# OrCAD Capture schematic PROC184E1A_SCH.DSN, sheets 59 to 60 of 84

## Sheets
59 67. x4 LANE_PCIe_CONN: size C; title: x1LANE PCIe INTERFACE; note: PROC184_SCH
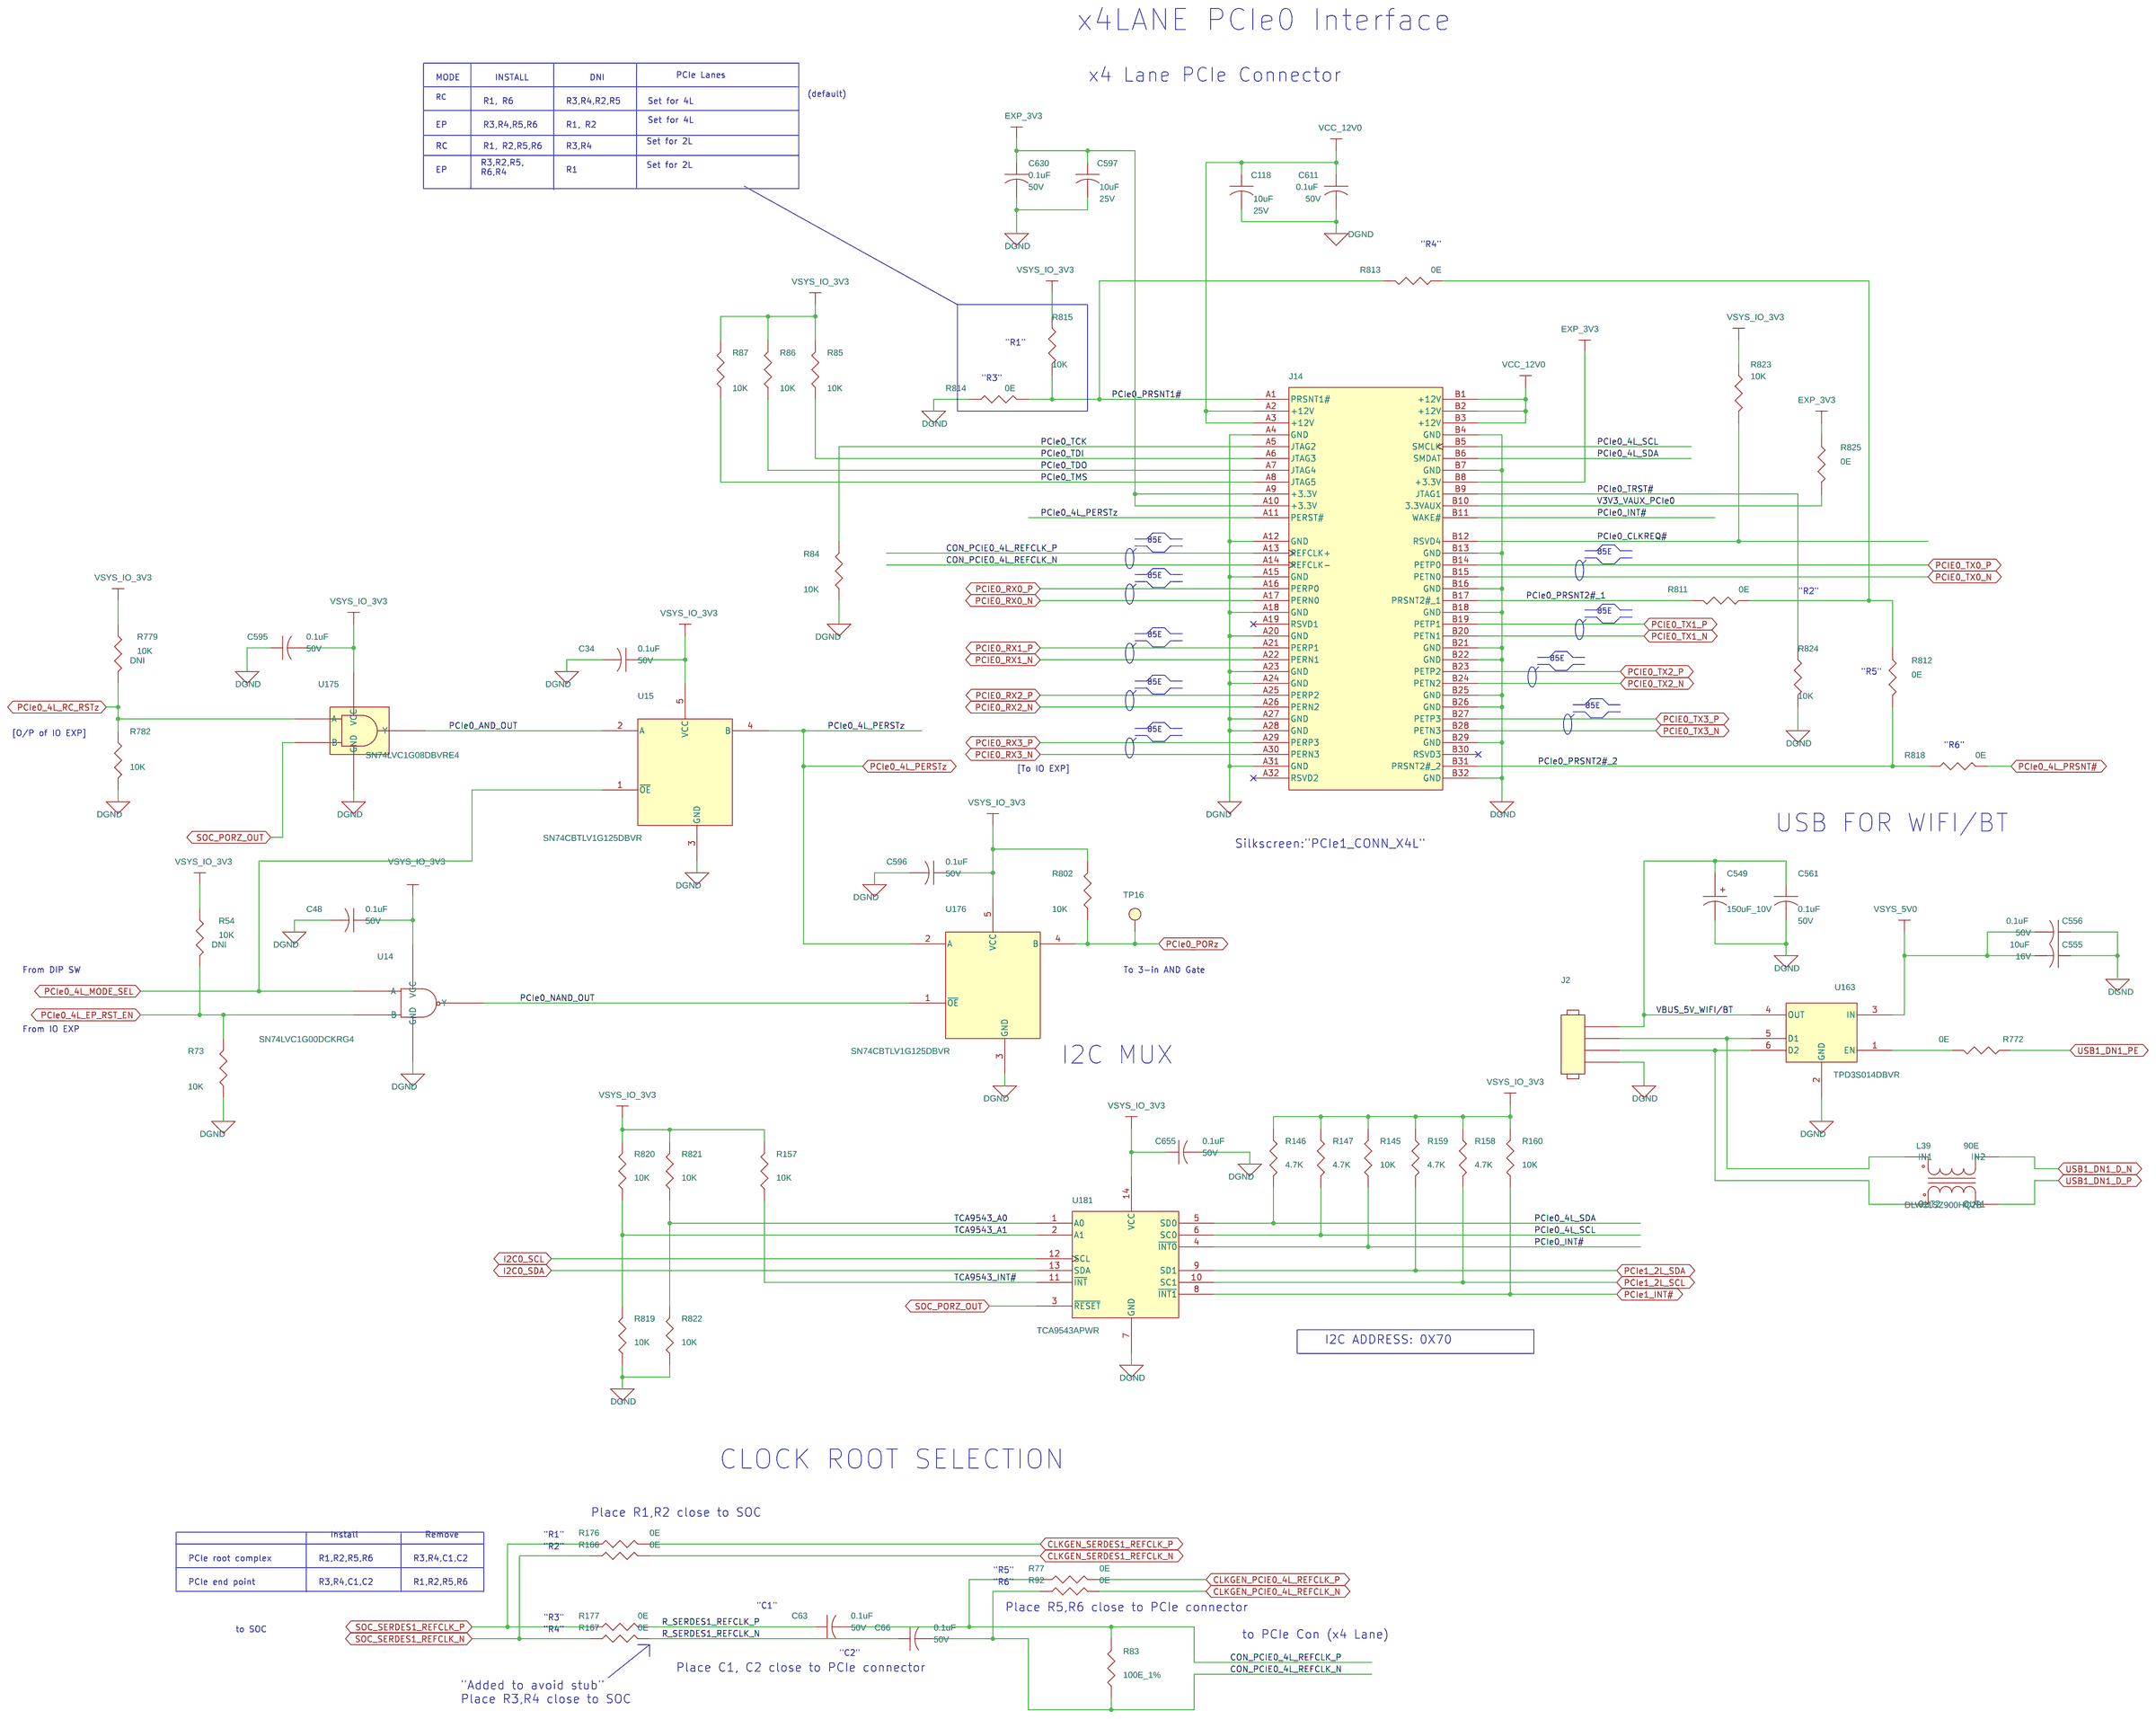
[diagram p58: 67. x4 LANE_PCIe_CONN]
60 68. x2 LANE_PCIe_CONN: size C; title: x2LANE PCIe Interface; note: PROC184_SCH
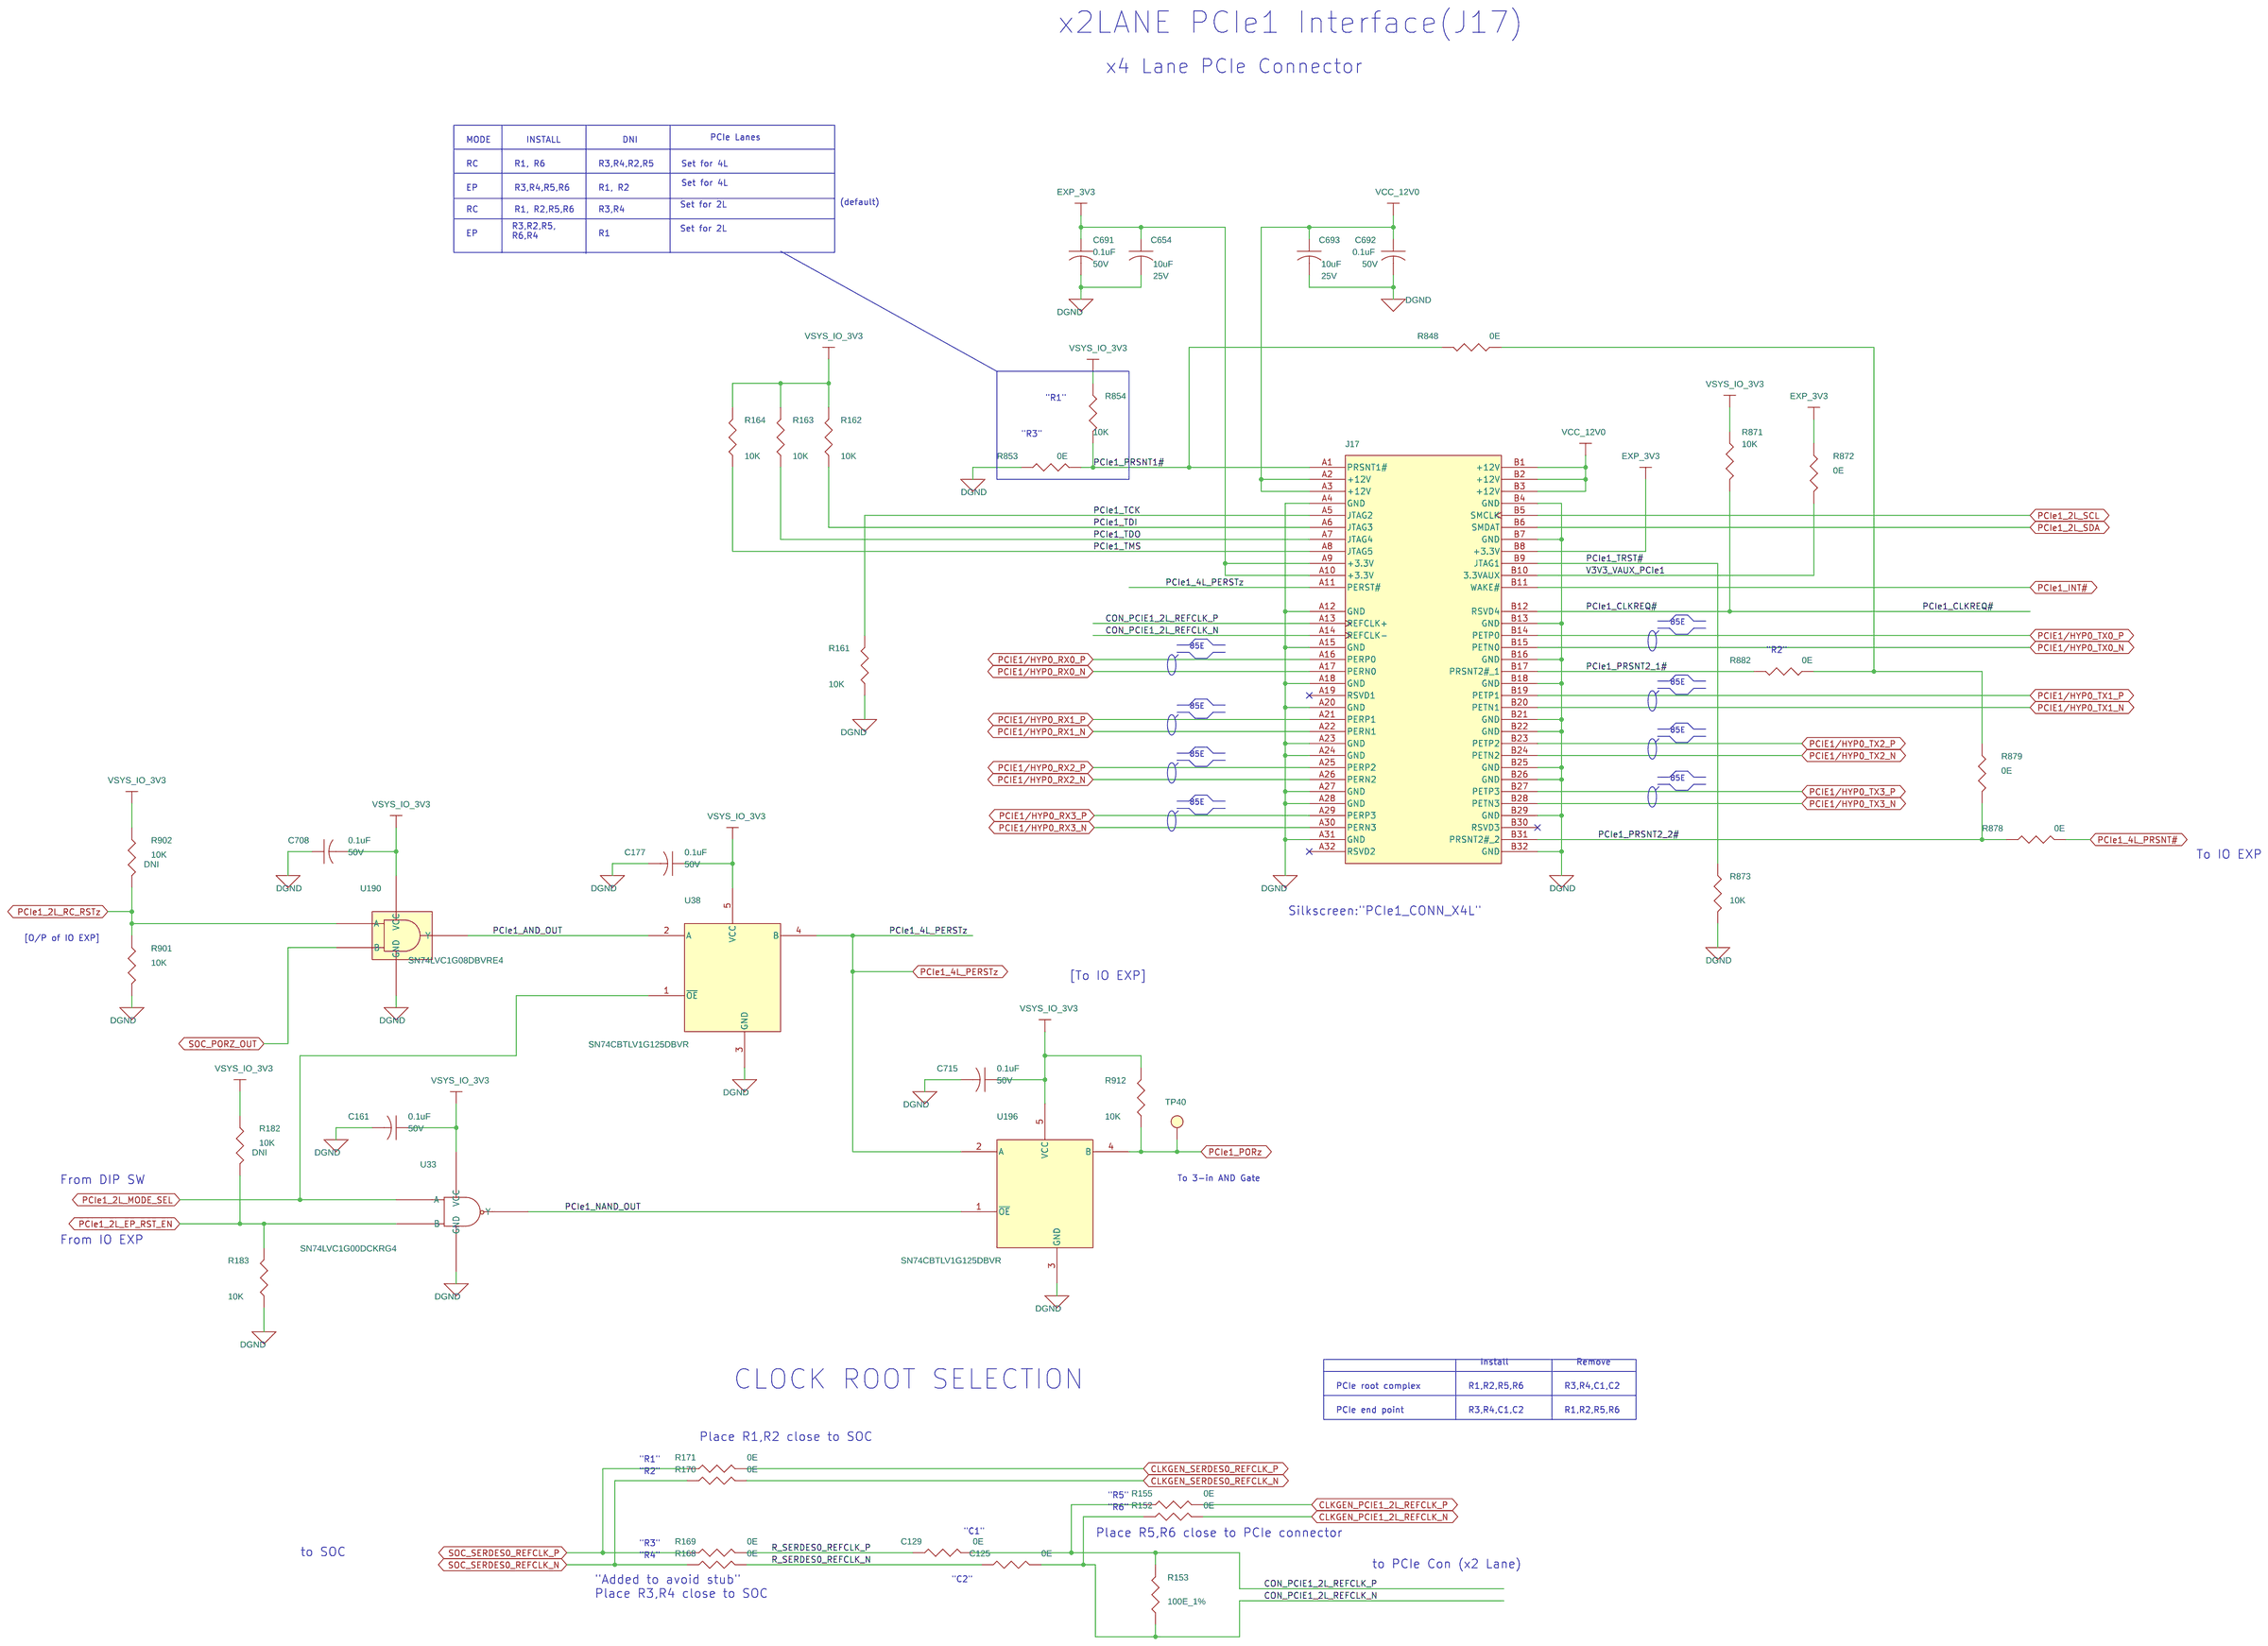
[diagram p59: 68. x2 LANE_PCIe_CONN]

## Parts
sheet 67. x4 LANE_PCIe_CONN
C34  0.1uF  [CAP0402_0-75]
C48  0.1uF  [CAP0402_0-75]
C63  0.1uF  [CAP0402_0-75]
C66  0.1uF  [CAP0402_0-75]
C118  10uF  [CAP0603_1-25]
C549  150uF_10V  [CAPT7343D_3-25]
C555  10uF  [CAP0805_1-5]
C556  0.1uF  [CAP0402_0-75]
C561  0.1uF  [CAP0402_0-75]
C595  0.1uF  [CAP0402_0-75]
C596  0.1uF  [CAP0402_0-75]
C597  10uF  [CAP0603_1-25]
C611  0.1uF  [CAP0402_0-75]
C630  0.1uF  [CAP0402_0-75]
C655  0.1uF  [CAP0402_0-75]
J2  HDR_1X4  [HDR_1X4_61300411121_S_T_8-6]
J14  CON_PCIE_2X32  [CON_PCIE2X32_10142333-10111_S_S_T_11]
L39  90E  [IND4_DLW21H_90X60_SMD_1-4]
R54  10K  [RES0402_0-5]
R73  10K  [RES0402_0-5]
R77  0E  [RES0402_0-5]
R83  100E_1%  [RES0402_0-5]
R84  10K  [RES0402_0-5]
R85  10K  [RES0402_0-5]
R86  10K  [RES0402_0-5]
R87  10K  [RES0402_0-5]
R92  0E  [RES0402_0-5]
R145  10K  [RES0402_0-5]
R146  4.7K  [RES0402_0-5]
R147  4.7K  [RES0402_0-5]
R157  10K  [RES0402_0-5]
R158  4.7K  [RES0402_0-5]
R159  4.7K  [RES0402_0-5]
R160  10K  [RES0402_0-5]
R166  0E  [RES0402_0-5]
R167  0E  [RES0402_0-5]
R176  0E  [RES0402_0-5]
R177  0E  [RES0402_0-5]
R772  0E  [RES0402_0-5]
R779  10K  [RES0402_0-5]
R782  10K  [RES0402_0-5]
R802  10K  [RES0402_0-5]
R811  0E  [RES0402_0-5]
R812  0E  [RES0402_0-5]
R813  0E  [RES0402_0-5]
R814  0E  [RES0402_0-5]
R815  10K  [RES0402_0-5]
R818  0E  [RES0402_0-5]
R819  10K  [RES0402_0-5]
R820  10K  [RES0402_0-5]
R821  10K  [RES0402_0-5]
R822  10K  [RES0402_0-5]
R823  10K  [RES0402_0-5]
R824  10K  [RES0402_0-5]
R825  0E  [RES0402_0-5]
TP16  TP40_SMD  [TP40_SMD]
U14  SN74LVC1G00DCKRG4  [SC70-5_1-1]
U15  SN74CBTLV1G125DBVR  [SOT23-5]
U163  TPD3S014DBVR  [SOT23-6_1-5]
U175  SN74LVC1G08DBVRE4  [SOT23-5]
U176  SN74CBTLV1G125DBVR  [SOT23-5]
U181  TCA9543APWR  [TSSOP14_25-59_205X180_1-2]
sheet 68. x2 LANE_PCIe_CONN
C125  0E  [RES0402_0-5]
C129  0E  [RES0402_0-5]
C161  0.1uF  [CAP0402_0-75]
C177  0.1uF  [CAP0402_0-75]
C654  10uF  [CAP0603_1-25]
C691  0.1uF  [CAP0402_0-75]
C692  0.1uF  [CAP0402_0-75]
C693  10uF  [CAP0603_1-25]
C708  0.1uF  [CAP0402_0-75]
C715  0.1uF  [CAP0402_0-75]
J17  CON_PCIE_2X32  [CON_PCIE2X32_10142333-10111_S_S_T_11]
R152  0E  [RES0402_0-5]
R153  100E_1%  [RES0402_0-5]
R155  0E  [RES0402_0-5]
R161  10K  [RES0402_0-5]
R162  10K  [RES0402_0-5]
R163  10K  [RES0402_0-5]
R164  10K  [RES0402_0-5]
R168  0E  [RES0402_0-5]
R169  0E  [RES0402_0-5]
R170  0E  [RES0402_0-5]
R171  0E  [RES0402_0-5]
R182  10K  [RES0402_0-5]
R183  10K  [RES0402_0-5]
R848  0E  [RES0402_0-5]
R853  0E  [RES0402_0-5]
R854  10K  [RES0402_0-5]
R871  10K  [RES0402_0-5]
R872  0E  [RES0402_0-5]
R873  10K  [RES0402_0-5]
R878  0E  [RES0402_0-5]
R879  0E  [RES0402_0-5]
R882  0E  [RES0402_0-5]
R901  10K  [RES0402_0-5]
R902  10K  [RES0402_0-5]
R912  10K  [RES0402_0-5]
TP40  TP40_SMD  [TP40_SMD]
U33  SN74LVC1G00DCKRG4  [SC70-5_1-1]
U38  SN74CBTLV1G125DBVR  [SOT23-5]
U190  SN74LVC1G08DBVRE4  [SOT23-5]
U196  SN74CBTLV1G125DBVR  [SOT23-5]

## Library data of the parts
C34 C48 C161 C177 C556 C561 C595 C596 C611 C630 C655 C691 C692 C708 C715 = CAP: CAP CERAMIC 0.1uF 50V 10% X7R 0402; Automotive Alternate_mfr_name: TDK; Automotive Alternate_mfr_part_number: CGA2B3X7R1H104K050BB; Chkd/date: MANIRAJA/261020; Crtd /date: ALVY/211020; Custom_Duty: 15%; Customs_HS_Code: 85322990; Direct Alternate_mfr_name: TDK; Direct Alternate_mfr_part_number: C1005X7R1H104K050BE; Distributor_name: DIGIKEY; Distributor_part_number: 490-10700-1-ND; Footprint Path: Y:\MIS_DATABASE\Library\ALTIUM_TOOL\PCB_FOOTPRINTS\Altium_Footprint_Lib.PcbLib; Height: 0.55MM; Library Path: Y:\MIS_DATABASE\Library\ALTIUM_TOOL\SCHEMATICS_PARTS\MS_DISCRETE_Library.schlib; Manufacturer: MURATA; Mfr_name: MURATA; Mfr_part_number: GRM155R71H104KE14D; Mistral Part No: 120011100014-R; Package: 0402; Part_type: CAPACITORS\CERAMIC; Project: J7_CP; RoHS: RoHS; Temperature: -55°C+125°C; Tolerance: 10%; Voltage: 50V; Wattage: NA; Weight: 3.1mg; Datasheet: Y:\MIS_DATABASE\DATASHEETS\CAPACITORS\GRM155R71H104KE14.PDF
C63 C66 = CAP: CAP CERAMIC 0.1uF 50V 10% X7R 0402; Assembly_Instruction: DNI; Automotive Alternate_mfr_name: TDK; Automotive Alternate_mfr_part_number: CGA2B3X7R1H104K050BB; Chkd/date: MANIRAJA/261020; Crtd /date: ALVY/211020; Custom_Duty: 15%; Customs_HS_Code: 85322990; Direct Alternate_mfr_name: TDK; Direct Alternate_mfr_part_number: C1005X7R1H104K050BE; Distributor_name: DIGIKEY; Distributor_part_number: 490-10700-1-ND; Footprint Path: Y:\MIS_DATABASE\Library\ALTIUM_TOOL\PCB_FOOTPRINTS\Altium_Footprint_Lib.PcbLib; Height: 0.55MM; Library Path: Y:\MIS_DATABASE\Library\ALTIUM_TOOL\SCHEMATICS_PARTS\MS_DISCRETE_Library.schlib; Manufacturer: MURATA; Mfr_name: MURATA; Mfr_part_number: GRM155R71H104KE14D; Mistral Part No: 120011100014-R; Package: 0402; Part_type: CAPACITORS\CERAMIC; Project: J7_CP; RoHS: RoHS; Temperature: -55°C+125°C; Tolerance: 10%; Voltage: 50V; Wattage: NA; Weight: 3.1mg; Datasheet: Y:\MIS_DATABASE\DATASHEETS\CAPACITORS\GRM155R71H104KE14.PDF
C118 C693 = CAP: CAP CERAMIC 10uF 25V 20% X5R 0603; Automotive Alternate_mfr_name: TDK; Automotive Alternate_mfr_part_number: CGA5L1X7R1H106K160AC; Chkd/date: MANIRAJA/040718; Crtd /date: MANIRAJA/040718; Custom_Duty: 15%; Customs_HS_Code: 85322990; Direct Alternate_mfr_name: SAMSUNG; Direct Alternate_mfr_part_number: CL31A106KBHNNNE; Distributor_name: DIGIKEY; Distributor_part_number: 490-10991-1-ND; Footprint Path: Y:\MIS_DATABASE\Library\ALTIUM_TOOL\PCB_FOOTPRINTS\Altium_Footprint_Lib.PcbLib; Height: 1.20MM; Library Path: Y:\MIS_DATABASE\Library\ALTIUM_TOOL\SCHEMATICS_PARTS\MS_DISCRETE_Library.schlib; Manufacturer: TDK CORPORATION; Mfr_name: MURATA; Mfr_part_number: ZRB18AR61E106ME01L; Mistral Part No: 120018070001-R; Package: 0603; Part_type: CAPACITORS\CERAMIC; Project: CABS_VME_DIO; RoHS: RoHS; Temperature: -55°C+85°C; Tolerance: 20%; Voltage: 25V; Wattage: NA; Weight: 2mg; Datasheet: Y:\MIS_DATABASE\DATASHEETS\CAPACITORS\ZRB18AR61E106ME01L.PDF
C549 = CAP_POL: CAP TANTALUM 150uF 10V 10% ESR 0.9E D7343; Chkd/date: MANIRAJA/240118; Crtd /date: MANIRAJA/240118; Custom_Duty: 15%; Customs_HS_Code: 85322990; Distributor_name: DIGIKEY; Distributor_part_number: 478-11241-1-ND; Footprint Path: Y:\MIS_DATABASE\Library\ALTIUM_TOOL\PCB_FOOTPRINTS\Altium_Footprint_Lib.PcbLib; Height: 3.10MM; Library Path: Y:\MIS_DATABASE\Library\ALTIUM_TOOL\SCHEMATICS_PARTS\MS_DISCRETE_Library.schlib; Manufacturer: AVX CORPORATION; Mfr_name: AVX CORPORATION; Mfr_part_number: TAJD157K010TNJV; Mistral Part No: 120018010025-R; Package: D7343; Part_type: CAPACITORS\TANTALUM; Project: TI_MAXIE_CPB; RoHS: RoHS; Temperature: -55°C+125°C; Tolerance: 10%; Voltage: 10V; Wattage: NA; Weight: 670mg; Datasheet: Y:\MIS_DATABASE\DATASHEETS\CAPACITORS\AVX-TAJ-SER.PDF
C555 = CAP: CAP CERAMIC 10uF 16V 10% X5R 0805; Automotive Alternate_mfr_name: TDK; Automotive Alternate_mfr_part_number: CGA4J1X7S1C106K125AC; Chkd/date: SHREESHAIL/220506; Crtd /date: MAZHAR/150506; Custom_Duty: 15%; Customs_HS_Code: 85322990; Direct Alternate_mfr_name: TDK; Direct Alternate_mfr_part_number: C2012X7S1C106K125AC; Distributor_name: DIGIKEY; Distributor_part_number: 490-3886-1-ND; Footprint Path: Y:\MIS_DATABASE\Library\ALTIUM_TOOL\PCB_FOOTPRINTS\Altium_Footprint_Lib.PcbLib; Height: 1.35MM; Library Path: Y:\MIS_DATABASE\Library\ALTIUM_TOOL\SCHEMATICS_PARTS\MS_DISCRETE_Library.schlib; Manufacturer: MURATA; Mfr_name: MURATA; Mfr_part_number: GRM21BR61C106KE15L; Mistral Part No: 120009030205-R; Package: 0805; Part_type: CAPACITORS\CERAMIC; Project: VOCERA; RoHS: RoHS; Temperature: -55°C+85°C; Tolerance: 10%; Voltage: 16V; Wattage: NA; Weight: 9.5mg; Datasheet: Y:\MIS_DATABASE\DATASHEETS\CAPACITORS\MURATA-GXX-SER_NOV17.PDF
C597 C654 = CAP: CAP CERAMIC 10uF 25V 20% X5R 0603; Automotive Alternate_mfr_name: MURATA; Automotive Alternate_mfr_part_number: GRT188R61E106ME13D; Chkd/date: MANIRAJA/040718; Crtd /date: MANIRAJA/040718; Custom_Duty: 15%; Customs_HS_Code: 85322990; Direct Alternate_mfr_name: TDK; Direct Alternate_mfr_part_number: C1608X5R1E106M080AC; Distributor_name: DIGIKEY; Distributor_part_number: 490-10991-1-ND; Footprint Path: Y:\MIS_DATABASE\Library\ALTIUM_TOOL\PCB_FOOTPRINTS\Altium_Footprint_Lib.PcbLib; Height: 1.20MM; Library Path: Y:\MIS_DATABASE\Library\ALTIUM_TOOL\SCHEMATICS_PARTS\MS_DISCRETE_Library.schlib; Manufacturer: MURATA; Mfr_name: MURATA; Mfr_part_number: ZRB18AR61E106ME01L; Mistral Part No: 120018070001-R; Package: 0603; Part_type: CAPACITORS\CERAMIC; Project: CABS_VME_DIO; RoHS: RoHS; Temperature: -55°C+85°C; Tolerance: 20%; Voltage: 25V; Wattage: NA; Weight: 2mg; Datasheet: Y:\MIS_DATABASE\DATASHEETS\CAPACITORS\ZRB18AR61E106ME01L.PDF
J2 = HEADER_4X1: CON HDR 1X4 2.54MM PITCH ST TH; Chkd/date: MANIRAJA/210918; Crtd /date: ALVY/210918; Custom_Duty: 24%; Customs_HS_Code: 85369090; Distributor_name: DIGIKEY; Distributor_part_number: 732-5317-ND; Footprint Path: Y:\MIS_DATABASE\Library\ALTIUM_TOOL\PCB_FOOTPRINTS\Altium_Footprint_Lib.PcbLib; Height: 8.54MM; Library Path: Y:\MIS_DATABASE\Library\ALTIUM_TOOL\SCHEMATICS_PARTS\MS_CONNECTOR_Library.schlib; Manufacturer: WURTH ELECTRONICS INC; Mfr_name: WURTH ELECTRONICS INC; Mfr_part_number: 61300411121; Mistral Part No: 150018090038-R; Package: THRU-HOLE; Part_type: CONNECTOR\HEADERS; Project: TI_60GHz-AOP; RoHS: RoHS; Temperature: -40°C+105°C; Tolerance: NA; Voltage: NA; Wattage: NA; Weight: 210mg; Datasheet: Y:\MIS_DATABASE\DATASHEETS\CONNECTORS\6130XXX.PDF
J14 J17 = CON_PCI_32X2_10142333: CON PCI EXPRESS 2X32 1.00MM PITCH FEMALE ST TH; Chkd/date: MANIRAJA/050718; Crtd /date: ALVY/050718; Custom_Duty: 24%; Customs_HS_Code: 85369090; Distributor_name: NA; Distributor_part_number: NA; Footprint Path: Y:\MIS_DATABASE\Library\ALTIUM_TOOL\PCB_FOOTPRINTS\Altium_Footprint_Lib.PcbLib; Height: 11.00MM; Library Path: Y:\MIS_DATABASE\Library\ALTIUM_TOOL\SCHEMATICS_PARTS\MS_CONNECTOR_Library.schlib; Manufacturer: AMPHENOL FCI; Mfr_name: AMPHENOL FCI; Mfr_part_number: 10142333-10111MLF; Mistral Part No: 150018070015; Package: THRU-HOLE; Part_type: CONNECTOR\PCI; Project: TI_J7SVB_PCIE_ADD-ON-CARD; RoHS: NA; Temperature: NA; Tolerance: NA; Voltage: NA; Wattage: NA; Weight: NA; Datasheet: Y:\MIS_DATABASE\DATASHEETS\CONNECTORS\10142333-XX.PDF
L39 = INDUCTOR_DLW31S: IND COMMON MODE CHOKE 90E 280mA SMD; Chkd/date: MANIRAJA/270619; Crtd /date: MANIRAJA/270619; Custom_Duty: 24%; Customs_HS_Code: 85437099; Distributor_name: NA; Distributor_part_number: NA; Footprint Path: Y:\MIS_DATABASE\Library\ALTIUM_TOOL\PCB_FOOTPRINTS\Altium_Footprint_Lib.PcbLib; Height: 1.40MM; Library Path: Y:\MIS_DATABASE\Library\ALTIUM_TOOL\SCHEMATICS_PARTS\MS_DISCRETE_Library.schlib; Manufacturer: MURATA; Mfr_name: MURATA; Mfr_part_number: DLW21SZ900HQ2B; Mistral Part No: 130019060035-R; Package: SMD; Part_type: INDUCTOR; Project: TI_J7ES_CP; RoHS: RoHS; Temperature: -40°C+105°C; Tolerance: NA; Voltage: NA; Wattage: NA; Weight: 11mg; Datasheet: Y:\MIS_DATABASE\DATASHEETS\DISCRETES\INDUCTORS\DLW21SZ900HQ2B.PDF
R54 R182 R779 R820 R821 R823 R871 R902 = RESISTOR: RES 10K 1/16W 5% 0402; Assembly_Instruction: DNI; Chkd/date: VASANTHA/061216; Crtd /date: MAZHAR/230805; Custom_Duty: 15%; Customs_HS_Code: 85332119; Distributor_name: DIGIKEY; Distributor_part_number: 311-10KJRCT-ND; Footprint Path: Y:\MIS_DATABASE\Library\ALTIUM_TOOL\PCB_FOOTPRINTS\Altium_Footprint_Lib.PcbLib; Height: 0.40MM; Library Path: Y:\MIS_DATABASE\Library\ALTIUM_TOOL\SCHEMATICS_PARTS\MS_DISCRETE_Library.schlib; Manufacturer: YAGEO AMERICA; Mfr_name: YAGEO AMERICA; Mfr_part_number: RC0402JR-0710KL; Mistral Part No: 110011060021-R; Package: 0402; Part_type: RESISTORS\FIXED; Project: HSE; RoHS: RoHS; Temperature: -55°C+155°C; Tolerance: 5%; Voltage: NA; Wattage: 1/16W; Weight: 0.65mg; Datasheet: Y:\MIS_DATABASE\DATASHEETS\RESISTORS\RCXXXXL-SER_MAR18.PDF
R73 R84-R87 R145 R157 R160-R164 R183 R782 R802 R815 R819 R822 R824 R854 R873 R901 R912 = RESISTOR: RES 10K 1/16W 5% 0402; Chkd/date: VASANTHA/061216; Crtd /date: MAZHAR/230805; Custom_Duty: 15%; Customs_HS_Code: 85332119; Distributor_name: DIGIKEY; Distributor_part_number: 311-10KJRCT-ND; Footprint Path: Y:\MIS_DATABASE\Library\ALTIUM_TOOL\PCB_FOOTPRINTS\Altium_Footprint_Lib.PcbLib; Height: 0.40MM; Library Path: Y:\MIS_DATABASE\Library\ALTIUM_TOOL\SCHEMATICS_PARTS\MS_DISCRETE_Library.schlib; Manufacturer: YAGEO AMERICA; Mfr_name: YAGEO AMERICA; Mfr_part_number: RC0402JR-0710KL; Mistral Part No: 110011060021-R; Package: 0402; Part_type: RESISTORS\FIXED; Project: HSE; RoHS: RoHS; Temperature: -55°C+155°C; Tolerance: 5%; Voltage: NA; Wattage: 1/16W; Weight: 0.65mg; Datasheet: Y:\MIS_DATABASE\DATASHEETS\RESISTORS\RCXXXXL-SER_MAR18.PDF
R77 R92 R152 R155 R166 R170 R171 R176 R772 R811 R812 R818 R825 R872 R878 R879 R882 = RESISTOR: RES 0E 1/10W JUMPER 0402; Chkd/date: VASANTHA/061216; Crtd /date: NAVEED/201014; Custom_Duty: 15%; Customs_HS_Code: 85332119; Distributor_name: DIGIKEY; Distributor_part_number: P0.0JCT-ND; Footprint Path: Y:\MIS_DATABASE\Library\ALTIUM_TOOL\PCB_FOOTPRINTS\Altium_Footprint_Lib.PcbLib; Height: 0.40MM; IBISSP_MODLES: VALUE REPEATING 2 TIME; Library Path: Y:\MIS_DATABASE\Library\ALTIUM_TOOL\SCHEMATICS_PARTS\MS_DISCRETE_Library.schlib; Manufacturer: PANASONIC-ECG; Mfr_name: PANASONIC-ECG; Mfr_part_number: ERJ-2GE0R00X; Mistral Part No: 110018030052-R; Package: 0402; Part_type: RESISTORS\FIXED; Project: AEGIS POM; RoHS: RoHS; Temperature: -55°C+155°C; Tolerance: NA; Voltage: NA; Wattage: 1/10W; Weight: 0.8mg; Datasheet: Y:\MIS_DATABASE\DATASHEETS\RESISTORS\PAN-ERJSER_NOV17.PDF
R83 R153 = RESISTOR: RES 100E 1/10W 1% 0402; Assembly_Instruction: DNI; Chkd/date: MANIRAJA/130617; Crtd /date: JEBRAN/040715; Custom_Duty: 15%; Customs_HS_Code: 85332119; Distributor_name: DIGIKEY; Distributor_part_number: P100LCT-ND; Footprint Path: Y:\MIS_DATABASE\Library\ALTIUM_TOOL\PCB_FOOTPRINTS\Altium_Footprint_Lib.PcbLib; Height: 0.40MM; Library Path: Y:\MIS_DATABASE\Library\ALTIUM_TOOL\SCHEMATICS_PARTS\MS_DISCRETE_Library.schlib; Manufacturer: PANASONIC-ECG; Mfr_name: PANASONIC-ECG; Mfr_part_number: ERJ-2RKF1000X; Mistral Part No: 110018020036-R; Package: 0402; Part_type: RESISTORS\FIXED; Project: CYPHY_FVB; RoHS: RoHS; Temperature: -55°C+155°C; Tolerance: 1%; Voltage: NA; Wattage: 1/10W; Weight: 0.8mg; Datasheet: Y:\MIS_DATABASE\DATASHEETS\RESISTORS\PAN-ERJSER_NOV17.PDF
R146 R147 R158 R159 = RESISTOR: RES 4.7K 1/16W 5% 0402; Chkd/date: VASANTHA/130516; Crtd /date: VASANTHA/130516; Custom_Duty: 15%; Customs_HS_Code: 85332119; Distributor_name: DIGIKEY; Distributor_part_number: 311-4.7KJRCT-ND; Footprint Path: Y:\MIS_DATABASE\Library\ALTIUM_TOOL\PCB_FOOTPRINTS\Altium_Footprint_Lib.PcbLib; Height: 0.40MM; Library Path: Y:\MIS_DATABASE\Library\ALTIUM_TOOL\SCHEMATICS_PARTS\MS_DISCRETE_Library.schlib; Manufacturer: YAGEO AMERICA; Mfr_name: YAGEO AMERICA; Mfr_part_number: RC0402JR-074K7L; Mistral Part No: 110011060001-R; Package: 0402; Part_type: RESISTORS\FIXED; Project: TMDXCSK368; RoHS: RoHS; Temperature: -55°C+155°C; Tolerance: 5%; Voltage: NA; Wattage: 1/16W; Weight: 0.65mg; Datasheet: Y:\MIS_DATABASE\DATASHEETS\RESISTORS\RCXXXXL-SER_MAR18.PDF
C125 C129 R167-R169 R177 R813 R814 R848 R853 = RESISTOR: RES 0E 1/10W JUMPER 0402; Assembly_Instruction: DNI; Chkd/date: VASANTHA/061216; Crtd /date: NAVEED/201014; Custom_Duty: 15%; Customs_HS_Code: 85332119; Distributor_name: DIGIKEY; Distributor_part_number: P0.0JCT-ND; Footprint Path: Y:\MIS_DATABASE\Library\ALTIUM_TOOL\PCB_FOOTPRINTS\Altium_Footprint_Lib.PcbLib; Height: 0.40MM; IBISSP_MODLES: VALUE REPEATING 2 TIME; Library Path: Y:\MIS_DATABASE\Library\ALTIUM_TOOL\SCHEMATICS_PARTS\MS_DISCRETE_Library.schlib; Manufacturer: PANASONIC-ECG; Mfr_name: PANASONIC-ECG; Mfr_part_number: ERJ-2GE0R00X; Mistral Part No: 110018030052-R; Package: 0402; Part_type: RESISTORS\FIXED; Project: AEGIS POM; RoHS: RoHS; Temperature: -55°C+155°C; Tolerance: NA; Voltage: NA; Wattage: 1/10W; Weight: 0.8mg; Datasheet: Y:\MIS_DATABASE\DATASHEETS\RESISTORS\PAN-ERJSER_NOV17.PDF
TP16 TP40 = TESTPOINT: TESTPOINT CIR 40 SMD; Chkd/date: MAZHAR/190505; Crtd /date: MAZHAR/190505; Distributor_name: NA; Distributor_part_number: NA; Footprint Path: Y:\MIS_DATABASE\Library\ALTIUM_TOOL\PCB_FOOTPRINTS\Altium_Footprint_Lib.PcbLib; Height: NA; Library Path: Y:\MIS_DATABASE\Library\ALTIUM_TOOL\SCHEMATICS_PARTS\MS_DISCRETE_Library.schlib; MECHANICAL 3D STEP FILE: NA; Manufacturer: LOCAL; Mfr_name: LOCAL; Mistral Part No: 130009030933; Package: SMD; Project: RAINIER-3; RoHS: NA; Temperature: NA; Tolerance: NA; Voltage: NA; Wattage: NA; Weight: NA; Datasheet: NA
U14 U33 = SN74LVC1G00_SC70-5: IC SINGLE 2-INPUT POSITIVE-NAND GATE SC70-5; Chkd/date: VASANTHA/080318; Crtd /date: MUDDU/150610; Custom_Duty: 15%; Customs_HS_Code: 85423100; Distributor_name: DIGIKEY; Distributor_part_number: SN74LVC1G00DCKRG4-ND; Footprint Path: Y:\MIS_DATABASE\Library\ALTIUM_TOOL\PCB_FOOTPRINTS\Altium_Footprint_Lib.PcbLib; Height: 1.10MM; Library Path: Y:\MIS_DATABASE\Library\ALTIUM_TOOL\SCHEMATICS_PARTS\MS_GATE_Library.schlib; Manufacturer: TEXAS INSTRUMENTS; Mfr_name: TEXAS INSTRUMENTS; Mistral Part No: 141010060014-R; Package: SC70-5; Part_type: ICS\DIGITAL\GATES; Project: CENTAURUS; RoHS: RoHS; Temperature: -40°C+125°C; Tolerance: NA; Voltage: NA; Wattage: NA; Weight: 20mg; Datasheet: Y:\MIS_DATABASE\DATASHEETS\ICS\DIGITAL\GATES\SN74LVC1G00D-2014.PDF
U15 U38 U176 U196 = SN74CBTLV1G125DBVR_SOT23-5: IC LOW VOLTAGE SINGLE FET BUS SW SOT23-5; Automotive Alternate_mfr_name: TEXAS INSTRUMENTS; Automotive Alternate_mfr_part_number: 74CBTLV1G125DBVRQ1; Chkd/date: BAVISH/010311; Crtd /date: MAZHAR/180907; Custom_Duty: 15%; Customs_HS_Code: 85423100; Distributor_name: DIGIKEY; Distributor_part_number: 296-9109-1-ND; Height: 1.45MM; Manufacturer: TEXAS INSTRUMENTS; Mfr_name: TEXAS INSTRUMENTS; Mistral Part No: 142009030140-R; Part_type: ICS\POWER; Project: HSE SERVO; RoHS: RoHS; Temperature: -40°C+85°C; Tolerance: NA; Voltage: NA; Wattage: NA; Weight: NA; Datasheet: Y:\MIS_DATABASE\DATASHEETS\ICS\POWER\SN74CBTLV1G125.PDF
U163 = TPD3S014D_SOT23-6: IC ESD PROTECTION FOR USB PORT WITH CURRENT LIMIT SWITCH SOT23-6; Chkd/date: VASANTHA/100217; Crtd /date: MANIRAJA/090217; Custom_Duty: 15%; Customs_HS_Code: 85423100; Distributor_name: DIGIKEY; Distributor_part_number: 296-38835-1-ND; Height: 1.45MM; Manufacturer: TEXAS INSTRUMENTS; Mfr_name: TEXAS INSTRUMENTS; Mistral Part No: 141017020013-R; Package: SOT23-6; Part_type: ICS\INTERFACE; Project: SD820_NANO_SOM; RoHS: RoHS; Temperature: -40°C+85°C; Tolerance: NA; Voltage: NA; Wattage: NA; Weight: 36mg; Datasheet: Y:\MIS_DATABASE\DATASHEETS\ICS\INTERFACE\TPD3S014XX.PDF
U175 U190 = SN74LVC1G08DBVRE4_SOT23-5: IC SINGLE 2-INPUT POSITIVE AND GATE SOT23-5; Automotive Alternate_mfr_name: TEXAS INSTRUMENTS; Automotive Alternate_mfr_part_number: SN74LVC1G08QDBVRQ1; Chkd/date: SUHAS/221010; Crtd /date: USMAN/151008; Custom_Duty: 15%; Customs_HS_Code: 85423100; Distributor_name: DIGIKEY; Distributor_part_number: SN74LVC1G08DBVRE4-ND; Height: 1.45MM; Manufacturer: TEXAS INSTRUMENTS; Mfr_name: TEXAS INSTRUMENTS; Mistral Part No: 141009060026-R; Part_type: ICS\DIGITAL\GATES; Project: KHAN_MAIN; RoHS: Sb/ Br FREE; Temperature: -40°C+85°C; Datasheet: Y:\MIS_DATABASE\DATASHEETS\ICS\DIGITAL\GATES\SN74LVC1G08.PDF
U181 = TCA9543APWR_TSSOP14: IC 2-CHANNEL I2C BUS SWITCH WITH INTERRUPT LOGIC AND RESET TSSOP14; Chkd/date: VASANTHA/060516; Crtd /date: VASANTHA/070316; Custom_Duty: 15%; Customs_HS_Code: 85423100; Distributor_name: DIGIKEY; Distributor_part_number: 296-42157-1-ND; Footprint Path: Y:\MIS_DATABASE\Library\ALTIUM_TOOL\PCB_FOOTPRINTS\Altium_Footprint_Lib.PcbLib; Height: 1.20MM; Library Path: Y:\MIS_DATABASE\Library\ALTIUM_TOOL\SCHEMATICS_PARTS\MS_BUSDRIVERTRANSCEIVER_Library.schlib; Manufacturer: TEXAS INSTRUMENTS; Mfr_name: TEXAS INSTRUMENTS; Mistral Part No: 141016030006-R; Package: TSSOP14; Part_type: ICS\DIGITAL\BUSTRANSCEIVER; Project: OCTASIC_3600; RoHS: RoHS; Temperature: -40°C+85°C; Tolerance: NA; Voltage: NA; Wattage: NA; Weight: NA; Datasheet: Y:\MIS_DATABASE\DATASHEETS\ICS\DIGITAL\BUSTRANSCEIVER\TCA9543A.PDF

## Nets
DGND: C34.2 C48.2 C118.2 C161.2 C177.2 C549.2 C555.1 C556.1 C561.2 C595.1 C596.2 C597.2 C611.2 C630.2 C654.2 C655.2 C691.2 C692.2 C693.2 C708.1 C715.2 J2.4 J14.A4(GND) J14.A12(GND) J14.A15(GND) J14.A18(GND) J14.A20(GND) J14.A23(GND) J14.A24(GND) J14.A27(GND) J14.A28(GND) J14.A31(GND) J14.B4(GND) J14.B7(GND) J14.B13(GND) J14.B16(GND) J14.B18(GND) J14.B21(GND) J14.B22(GND) J14.B25(GND) J14.B26(GND) J14.B29(GND) J14.B32(GND) J17.A4(GND) J17.A12(GND) J17.A15(GND) J17.A18(GND) J17.A20(GND) J17.A23(GND) J17.A24(GND) J17.A27(GND) J17.A28(GND) J17.A31(GND) J17.B4(GND) J17.B7(GND) J17.B13(GND) J17.B16(GND) J17.B18(GND) J17.B21(GND) J17.B22(GND) J17.B25(GND) J17.B26(GND) J17.B29(GND) J17.B32(GND) R73.1 R84.1 R161.1 R183.1 R782.2 R814.1 R819.1 R822.1 R824.2 R853.1 R873.2 R901.2 U14.3(GND) U15.3(GND) U33.3(GND) U38.3(GND) U163.2(GND) U175.3(GND) U176.3(GND) U181.7(GND) U190.3(GND) U196.3(GND) ; also on sheet 11 12 13 14 15 16 17 18 20 21 22 23 24 25 26 27 28 29 30 31 32 33 34 35 36 37 38 39 40 41 42 43 44 45 46 47 48 49 50 51 52 53 54 55 56 57 58 61 62 63 64 65 66 67 68 69 70 71 72 73 76 77 78 79 81 82 83 84
V3V3_VAUX_PCIe0: J14.B10(3.3VAUX) R825.2
V3V3_VAUX_PCIe1: J17.B10(3.3VAUX) R872.2
VCC_12V0: C118.1 C611.1 C692.1 C693.1 J14.A2(+12V) J14.A3(+12V) J14.B1(+12V) J14.B2(+12V) J14.B3(+12V) J17.A2(+12V) J17.A3(+12V) J17.B1(+12V) J17.B2(+12V) J17.B3(+12V) ; also on sheet 30 31 46 50 53 64 66 83
CLKGEN_PCIE0_4L_REFCLK_N: R92.2 ; also on sheet 32
CLKGEN_PCIE0_4L_REFCLK_P: R77.2 ; also on sheet 32
CLKGEN_PCIE1_2L_REFCLK_N: R152.2 ; also on sheet 32
CLKGEN_PCIE1_2L_REFCLK_P: R155.2 ; also on sheet 32
CLKGEN_SERDES0_REFCLK_N: R170.2 ; also on sheet 32
CLKGEN_SERDES0_REFCLK_P: R171.2 ; also on sheet 32
CLKGEN_SERDES1_REFCLK_N: R166.2 ; also on sheet 32
CLKGEN_SERDES1_REFCLK_P: R176.2 ; also on sheet 32
CON_PCIE0_4L_REFCLK_N: C66.2 J14.A14(REFCLK-) R83.2 R92.1
CON_PCIE0_4L_REFCLK_P: C63.2 J14.A13(REFCLK+) R77.1 R83.1
CON_PCIE1_2L_REFCLK_N: C125.2 J17.A14(REFCLK-) R152.1 R153.2
CON_PCIE1_2L_REFCLK_P: C129.2 J17.A13(REFCLK+) R153.1 R155.1
EXP_3V3: C597.1 C630.1 C654.1 C691.1 J14.A9(+3.3V) J14.A10(+3.3V) J14.B8(+3.3V) J17.A9(+3.3V) J17.A10(+3.3V) J17.B8(+3.3V) R825.1 R872.1 ; also on sheet 30 31 65
I2C0_SCL: U181.12(SCL) ; also on sheet 20 32 33 34 38 58
I2C0_SDA: U181.13(SDA) ; also on sheet 20 32 33 34 38 58
PCIe0_4L_EP_RST_EN: R54.2 R73.2 U14.2(B) ; also on sheet 38
PCIe0_4L_MODE_SEL: U14.1(A) U15.1(~{OE}) ; also on sheet 35 38
PCIe0_4L_PERSTz: J14.A11(PERST#) U15.4(B) U176.2(A) ; also on sheet 38
PCIe0_4L_PRSNT#: R818.2 ; also on sheet 38
PCIe0_4L_RC_RSTz: R779.2 R782.1 U175.1(A) ; also on sheet 38
PCIe0_4L_SCL: J14.B5(SMCLK) R147.2 U181.6(SC0)
PCIe0_4L_SDA: J14.B6(SMDAT) R146.2 U181.5(SD0)
PCIe0_AND_OUT: U15.2(A) U175.4(Y)
PCIe0_CLKREQ#: J14.B12(RSVD4) R823.2
PCIe0_INT#: J14.B11(WAKE#) R145.1 U181.4(~{INT0})
PCIe0_NAND_OUT: U14.4(Y) U176.1(~{OE})
PCIe0_PORz: R802.1 TP16.1(TP) U176.4(B) ; also on sheet 36
PCIe0_PRSNT1#: J14.A1(PRSNT1#) R813.2 R814.2 R815.2
PCIe0_PRSNT2#_1: J14.B17(PRSNT2#_1) R811.2
PCIe0_PRSNT2#_2: J14.B31(PRSNT2#_2) R812.2 R818.1
PCIE0_RX0_N: J14.A17(PERN0) ; also on sheet 13
PCIE0_RX0_P: J14.A16(PERP0) ; also on sheet 13
PCIE0_RX1_N: J14.A22(PERN1) ; also on sheet 13
PCIE0_RX1_P: J14.A21(PERP1) ; also on sheet 13
PCIE0_RX2_N: J14.A26(PERN2) ; also on sheet 13
PCIE0_RX2_P: J14.A25(PERP2) ; also on sheet 13
PCIE0_RX3_N: J14.A30(PERN3) ; also on sheet 13
PCIE0_RX3_P: J14.A29(PERP3) ; also on sheet 13
PCIe0_TCK: J14.A5(JTAG2) R84.2
PCIe0_TDI: J14.A6(JTAG3) R85.1
PCIe0_TDO: J14.A7(JTAG4) R86.1
PCIe0_TMS: J14.A8(JTAG5) R87.1
PCIe0_TRST#: J14.B9(JTAG1) R824.1
PCIE0_TX0_N: J14.B15(PETN0) ; also on sheet 13
PCIE0_TX0_P: J14.B14(PETP0) ; also on sheet 13
PCIE0_TX1_N: J14.B20(PETN1) ; also on sheet 13
PCIE0_TX1_P: J14.B19(PETP1) ; also on sheet 13
PCIE0_TX2_N: J14.B24(PETN2) ; also on sheet 13
PCIE0_TX2_P: J14.B23(PETP2) ; also on sheet 13
PCIE0_TX3_N: J14.B28(PETN3) ; also on sheet 13
PCIE0_TX3_P: J14.B27(PETP3) ; also on sheet 13
PCIE1/HYP0_RX0_N: J17.A17(PERN0) ; also on sheet 12
PCIE1/HYP0_RX0_P: J17.A16(PERP0) ; also on sheet 12
PCIE1/HYP0_RX1_N: J17.A22(PERN1) ; also on sheet 12
PCIE1/HYP0_RX1_P: J17.A21(PERP1) ; also on sheet 12
PCIE1/HYP0_RX2_N: J17.A26(PERN2) ; also on sheet 12
PCIE1/HYP0_RX2_P: J17.A25(PERP2) ; also on sheet 12
PCIE1/HYP0_RX3_N: J17.A30(PERN3) ; also on sheet 12
PCIE1/HYP0_RX3_P: J17.A29(PERP3) ; also on sheet 12
PCIE1/HYP0_TX0_N: J17.B15(PETN0) ; also on sheet 12
PCIE1/HYP0_TX0_P: J17.B14(PETP0) ; also on sheet 12
PCIE1/HYP0_TX1_N: J17.B20(PETN1) ; also on sheet 12
PCIE1/HYP0_TX1_P: J17.B19(PETP1) ; also on sheet 12
PCIE1/HYP0_TX2_N: J17.B24(PETN2) ; also on sheet 12
PCIE1/HYP0_TX2_P: J17.B23(PETP2) ; also on sheet 12
PCIE1/HYP0_TX3_N: J17.B28(PETN3) ; also on sheet 12
PCIE1/HYP0_TX3_P: J17.B27(PETP3) ; also on sheet 12
PCIe1_2L_EP_RST_EN: R182.2 R183.2 U33.2(B) ; also on sheet 38
PCIe1_2L_MODE_SEL: U33.1(A) U38.1(~{OE}) ; also on sheet 35 38
PCIe1_2L_RC_RSTz: R901.1 R902.2 U190.1(A) ; also on sheet 38
PCIe1_2L_SCL: J17.B5(SMCLK) R158.2 U181.10(SC1)
PCIe1_2L_SDA: J17.B6(SMDAT) R159.2 U181.9(SD1)
PCIe1_4L_PERSTz: J17.A11(PERST#) U38.4(B) U196.2(A) ; also on sheet 38
PCIe1_4L_PRSNT#: R878.2 ; also on sheet 38
PCIe1_AND_OUT: U38.2(A) U190.4(Y)
PCIe1_CLKREQ#: J17.B12(RSVD4) R871.2
PCIe1_INT#: J17.B11(WAKE#) R160.1 U181.8(~{INT1})
PCIe1_NAND_OUT: U33.4(Y) U196.1(~{OE})
PCIe1_PORz: R912.1 TP40.1(TP) U196.4(B) ; also on sheet 36
PCIe1_PRSNT1#: J17.A1(PRSNT1#) R848.2 R853.2 R854.2
PCIe1_PRSNT2_1#: J17.B17(PRSNT2#_1) R882.2
PCIe1_PRSNT2_2#: J17.B31(PRSNT2#_2) R878.1 R879.2
PCIe1_TCK: J17.A5(JTAG2) R161.2
PCIe1_TDI: J17.A6(JTAG3) R162.1
PCIe1_TDO: J17.A7(JTAG4) R163.1
PCIe1_TMS: J17.A8(JTAG5) R164.1
PCIe1_TRST#: J17.B9(JTAG1) R873.1
R_SERDES0_REFCLK_N: C125.1 R168.2
R_SERDES0_REFCLK_P: C129.1 R169.2
R_SERDES1_REFCLK_N: C66.1 R167.2
R_SERDES1_REFCLK_P: C63.1 R177.2
SOC_PORZ_OUT: U175.2(B) U181.3(~{RESET}) U190.2(B) ; also on sheet 18 30 32 37 43 51 56 62 69
SOC_SERDES0_REFCLK_N: R168.1 R170.1 ; also on sheet 12
SOC_SERDES0_REFCLK_P: R169.1 R171.1 ; also on sheet 12
SOC_SERDES1_REFCLK_N: R166.1 R167.1 ; also on sheet 13
SOC_SERDES1_REFCLK_P: R176.1 R177.1 ; also on sheet 13
TCA9543_A0: R821.1 R822.2 U181.1(A0)
TCA9543_A1: R819.2 R820.1 U181.2(A1)
TCA9543_INT#: R157.1 U181.11(~{INT})
USB1_DN1_D_N: L39.2(IN2) ; also on sheet 51
USB1_DN1_D_P: L39.3(OUT1) ; also on sheet 51
USB1_DN1_PE: R772.2 ; also on sheet 51
VBUS_5V_WIFI/BT: C549.1 C561.1 J2.1 U163.4(OUT)
VSYS_5V0: C555.2 C556.2 U163.3(IN) ; also on sheet 20 30 31 50 52 65 68 72 81 82 83 84
VSYS_IO_3V3: C34.1 C48.1 C161.1 C177.1 C595.2 C596.1 C655.1 C708.2 C715.1 R54.1 R85.2 R86.2 R87.2 R145.2 R146.1 R147.1 R157.2 R158.1 R159.1 R160.2 R162.2 R163.2 R164.2 R182.1 R779.1 R802.2 R815.1 R820.2 R821.2 R823.1 R854.1 R871.1 R902.1 R912.2 U14.5(VCC) U15.5(VCC) U33.5(VCC) U38.5(VCC) U175.5(VCC) U176.5(VCC) U181.14(VCC) U190.5(VCC) U196.5(VCC) ; also on sheet 18 20 22 24 29 30 31 32 33 35 36 37 38 40 41 42 43 45 46 48 50 51 53 56 57 58 61 65 66 68 75 81 82
N23722671: R811.1 R812.1 R813.1
N23768120: R848.1 R879.1 R882.1
N24575373: J2.2 L39.1(IN1) U163.5(D1)
N24575375: J2.3 L39.4(OUT2) U163.6(D2)
N28381888: R772.1 U163.1(EN)

Not connected (* = marked no-connect by the designer): J14 A19(RSVD1)* A32(RSVD2)* B30(RSVD3)*; J17 A19(RSVD1)* A32(RSVD2)* B30(RSVD3)*

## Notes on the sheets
sheet 59
- x4LANE PCIe0 Interface
- x4 Lane PCIe Connector
- MODE
- INSTALL
- DNI
- PCIe Lanes
- RC
- (default)
- R1, R6
- R3,R4,R2,R5
- Set for 4L
- EP
- R3,R4,R5,R6
- R1, R2
- Set for 4L
- Set for 2L
- RC
- R1, R2,R5,R6
- R3,R4
- EP
- R3,R2,R5,
  R6,R4
- R1
- Set for 2L
- "R4"
- "R1"
- "R3"
- 85E
- 85E
- 85E
- "R2"
- 85E
- 85E
- 85E
- "R5"
- 85E
- 85E
- 85E
- [O/P of IO EXP]
- "R6"
- [To IO EXP]
- USB FOR WIFI/BT
- Silkscreen:"PCIe1_CONN_X4L"
- From DIP SW
- To 3-in AND Gate
- From IO EXP
- I2C MUX
- I2C ADDRESS: 0X70
- CLOCK ROOT SELECTION
- Place R1,R2 close to SOC
- Install
- Remove
- "R1"
- "R2"
- PCIe root complex
- R1,R2,R5,R6
- R3,R4,C1,C2
- PCIe end point
- R3,R4,C1,C2
- R1,R2,R5,R6
- "R5"
- "R6"
- "C1"
- Place R5,R6 close to PCIe connector
- "R3"
- to SOC
- "R4"
- to PCIe Con (x4 Lane)
- Place C1, C2 close to PCIe connector
- "C2"
- "Added to avoid stub"
  Place R3,R4 close to SOC
sheet 60
- x2LANE PCIe1 Interface(J17)
- x4 Lane PCIe Connector
- MODE
- INSTALL
- DNI
- PCIe Lanes
- RC
- R1, R6
- R3,R4,R2,R5
- Set for 4L
- EP
- R3,R4,R5,R6
- R1, R2
- Set for 4L
- (default)
- RC
- R1, R2,R5,R6
- R3,R4
- Set for 2L
- R3,R2,R5,
  R6,R4
- Set for 2L
- EP
- R1
- "R1"
- "R3"
- 85E
- 85E
- "R2"
- 85E
- 85E
- 85E
- 85E
- 85E
- 85E
- To IO EXP
- Silkscreen:"PCIe1_CONN_X4L"
- [O/P of IO EXP]
- [To IO EXP]
- From DIP SW
- To 3-in AND Gate
- From IO EXP
- Install
- Remove
- CLOCK ROOT SELECTION
- PCIe root complex
- R1,R2,R5,R6
- R3,R4,C1,C2
- PCIe end point
- R3,R4,C1,C2
- R1,R2,R5,R6
- Place R1,R2 close to SOC
- "R1"
- "R2"
- "R5"
- "R6"
- "C1"
- Place R5,R6 close to PCIe connector
- to SOC
- "R3"
- "R4"
- to PCIe Con (x2 Lane)
- "Added to avoid stub"
  Place R3,R4 close to SOC
- "C2"
